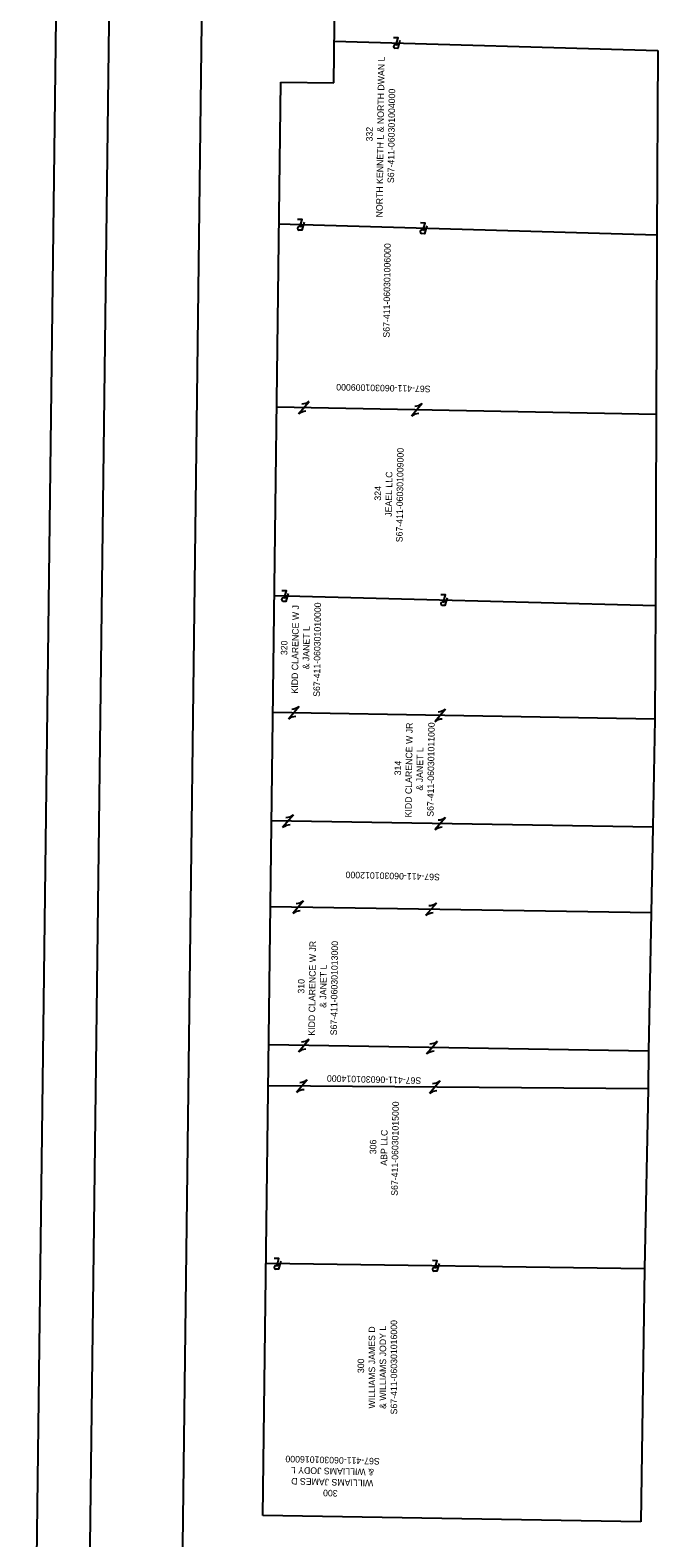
# Model space of a CAD drawing. Extents: x 1652206 to 1653153, y 604222 to 614600.
# Drawn here: x 1652507 to 1652744, y 607973 to 608542 of the extents above; entities that cross this region are included whole.
import ezdxf

# ---------------------------------------------------------------- set-up
doc = ezdxf.new("R2010")
doc.units = 0
for name, color, linetype in [('_CIVIL_CONSTRUCTION', 7, 'Continuous'), ('DT_X_Contour_Minor', 7, 'Continuous'), ('GE_P_Alignment_100_Bearings', 7, 'Continuous'), ('GE_P_Alignment_100_Cardinal_Points', 7, 'Continuous'), ('GE_P_Alignment_100_Distances', 7, 'Continuous')]:
    doc.layers.add(name, color=color, linetype=linetype)

msp = doc.modelspace()

# ---------------------------------------------------------------- linework, layer by layer
at = {"layer": '_CIVIL_CONSTRUCTION'}
msp.add_line((1652550.86, 606872.07), (1652575.14, 608815.48), dxfattribs=at)
at = {"layer": 'DT_X_Contour_Minor'}
msp.add_lwpolyline([(1652527.01, 607765.18), (1652507.01, 607765.43), (1652518.27, 608666.13)], dxfattribs=at)
at = {"layer": 'GE_P_Alignment_100_Bearings'}
for p, q in [((1652621.66, 608537.35), (1652743.59, 608533.88)), ((1652645.94, 608536.04), (1652644.64, 608536.07)), ((1652645.15, 608536.68), (1652645.15, 608536.68)), ((1652743.59, 608533.88), (1652743.27, 608464.32)), ((1652743.27, 608464.32), (1652600.8, 608468.46)), ((1652609.78, 608467.57), (1652608.48, 608467.61)), ((1652608.99, 608468.22), (1652608.99, 608468.22)), ((1652656.06, 608466.23), (1652654.76, 608466.27)), ((1652655.27, 608466.88), (1652655.27, 608466.88)), ((1652743.27, 608464.32), (1652742.93, 608396.68)), ((1652742.93, 608396.68), (1652599.94, 608399.55)), ((1652608.13, 608396.99), (1652612.23, 608401.7)), ((1652610.18, 608399.35), (1652610.18, 608399.35)), ((1652654.8, 608400.85), (1652650.71, 608396.13)), ((1652652.76, 608398.49), (1652652.76, 608398.49)), ((1652742.93, 608396.68), (1652742.65, 608324.68)), ((1652742.65, 608324.68), (1652599.05, 608328.4)), ((1652603.79, 608327.66), (1652602.5, 608327.69)), ((1652603.01, 608328.3), (1652603.01, 608328.3)), ((1652663.77, 608326.1), (1652662.48, 608326.14)), ((1652662.99, 608326.75), (1652662.99, 608326.75)), ((1652742.65, 608324.68), (1652742.51, 608281.9)), ((1652742.51, 608281.9), (1652598.5, 608284.5)), ((1652608.43, 608286.72), (1652604.34, 608281.99)), ((1652606.39, 608284.36), (1652606.39, 608284.36)), ((1652663.58, 608285.73), (1652659.5, 608281)), ((1652661.54, 608283.36), (1652661.54, 608283.36)), ((1652742.51, 608281.9), (1652741.75, 608241.28)), ((1652741.75, 608241.28), (1652597.99, 608243.6)), ((1652606.24, 608245.86), (1652602.16, 608241.13)), ((1652604.2, 608243.5), (1652604.2, 608243.5)), ((1652663.59, 608244.94), (1652659.51, 608240.21)), ((1652661.55, 608242.57), (1652661.55, 608242.57)), ((1652741.75, 608241.28), (1652741.13, 608208.94)), ((1652741.13, 608208.94), (1652597.59, 608211.29)), ((1652610.09, 608213.49), (1652606.01, 608208.75)), ((1652608.05, 608211.12), (1652608.05, 608211.12)), ((1652660.14, 608212.67), (1652656.06, 608207.93)), ((1652658.1, 608210.3), (1652658.1, 608210.3)), ((1652741.13, 608208.94), (1652740.11, 608156.88)), ((1652740.11, 608156.88), (1652596.94, 608159.21)), ((1652608.11, 608156.63), (1652612.18, 608161.36)), ((1652610.15, 608158.99), (1652610.15, 608158.99)), ((1652656.44, 608155.84), (1652660.52, 608160.58)), ((1652658.48, 608158.21), (1652658.48, 608158.21)), ((1652740.11, 608156.88), (1652739.91, 608142.62)), ((1652739.91, 608142.62), (1652596.75, 608143.82)), ((1652611.47, 608146.1), (1652607.43, 608141.34)), ((1652609.45, 608143.72), (1652609.45, 608143.72)), ((1652661.52, 608145.68), (1652657.48, 608140.92)), ((1652659.5, 608143.3), (1652659.5, 608143.3)), ((1652739.91, 608142.62), (1652738.57, 608074.84)), ((1652738.57, 608074.84), (1652595.91, 608076.8)), ((1652601.01, 608076.11), (1652599.72, 608076.12)), ((1652600.22, 608076.74), (1652600.22, 608076.74)), ((1652660.67, 608075.29), (1652659.37, 608075.31)), ((1652659.87, 608075.92), (1652659.87, 608075.92)), ((1652738.57, 608074.84), (1652737.21, 607979.54))]:
    msp.add_line(p, q, dxfattribs=at)
for points in [[(1652644.86, 608535.73), (1652645.74, 608538.66), (1652643.99, 608538.71)], [(1652646.4, 608537.62), (1652645.54, 608534.67), (1652644.5, 608534.71)], [(1652608.7, 608467.27), (1652609.58, 608470.2), (1652607.83, 608470.25)], [(1652610.24, 608469.15), (1652609.38, 608466.21), (1652608.34, 608466.24)], [(1652654.98, 608465.92), (1652655.86, 608468.86), (1652654.11, 608468.91)], [(1652656.52, 608467.81), (1652655.66, 608464.87), (1652654.62, 608464.9)], [(1652602.72, 608327.35), (1652603.59, 608330.28), (1652601.84, 608330.33)], [(1652604.26, 608329.24), (1652603.4, 608326.29), (1652602.36, 608326.32)], [(1652662.69, 608325.79), (1652663.56, 608328.73), (1652661.82, 608328.78)], [(1652664.23, 608327.68), (1652663.37, 608324.74), (1652662.34, 608324.77)], [(1652599.94, 608075.78), (1652600.77, 608078.73), (1652599.03, 608078.75)], [(1652601.45, 608077.69), (1652600.63, 608074.74), (1652599.6, 608074.75)], [(1652659.59, 608074.97), (1652660.43, 608077.91), (1652658.68, 608077.94)], [(1652661.11, 608076.87), (1652660.29, 608073.92), (1652659.25, 608073.94)]]:
    msp.add_lwpolyline(points, dxfattribs=at)
for centre, radius, start, end in [((1652644.63, 608535.38), 0.69, 88.8416, 259.6987), ((1652608.47, 608466.92), 0.69, 88.8087, 259.6658), ((1652654.75, 608465.58), 0.69, 88.8087, 259.6658), ((1652611.21, 608392.62), 5.34, 92.5458, 125.1883), ((1652609.15, 608406.07), 5.34, 272.5458, 305.1883), ((1652653.78, 608391.77), 5.34, 92.5458, 125.1883), ((1652651.73, 608405.21), 5.34, 272.5458, 305.1883), ((1652602.49, 608327), 0.69, 88.9868, 259.8439), ((1652662.46, 608325.45), 0.69, 88.9868, 259.8439), ((1652607.43, 608277.64), 5.34, 92.6621, 125.3047), ((1652605.35, 608291.08), 5.34, 272.6621, 305.3047), ((1652660.5, 608290.08), 5.34, 272.6621, 305.3047), ((1652662.58, 608276.64), 5.34, 92.6621, 125.3047), ((1652603.15, 608250.21), 5.34, 272.7732, 305.4157), ((1652660.5, 608249.29), 5.34, 272.7732, 305.4157), ((1652605.26, 608236.78), 5.34, 92.7732, 125.4157), ((1652662.6, 608235.86), 5.34, 92.7732, 125.4157), ((1652609.1, 608204.4), 5.34, 92.7574, 125.3999), ((1652607, 608217.84), 5.34, 272.7574, 305.3999), ((1652657.05, 608217.02), 5.34, 272.7574, 305.3999), ((1652659.15, 608203.58), 5.34, 92.7574, 125.3999), ((1652609.09, 608165.71), 5.34, 272.765, 305.4075), ((1652657.43, 608164.93), 5.34, 272.765, 305.4075), ((1652611.2, 608152.28), 5.34, 92.765, 125.4075), ((1652659.54, 608151.49), 5.34, 92.765, 125.4075), ((1652610.55, 608137.01), 5.34, 93.2137, 125.8563), ((1652608.34, 608150.43), 5.34, 273.2137, 305.8563), ((1652660.61, 608136.59), 5.34, 93.2137, 125.8563), ((1652658.4, 608150.01), 5.34, 273.2137, 305.8563), ((1652599.71, 608075.43), 0.69, 89.6859, 260.543), ((1652659.37, 608074.62), 0.69, 89.6859, 260.543)]:
    msp.add_arc(centre, radius, start, end, dxfattribs=at)
at = {"layer": 'GE_P_Alignment_100_Distances'}
for p, q in [((1652621.47, 608521.72), (1652624.44, 608759.7)), ((1652525.46, 607640.72), (1652538.25, 608664.92)), ((1652594.72, 607981.92), (1652601.47, 608521.97)), ((1652601.47, 608521.97), (1652621.47, 608521.72)), ((1652737.21, 607979.54), (1652594.72, 607981.92))]:
    msp.add_line(p, q, dxfattribs=at)

# ---------------------------------------------------------------- texts
at = {"layer": 'GE_P_Alignment_100_Cardinal_Points'}
for s, height, rotation, p in [('NORTH KENNETH L & NORTH DWAN L', 2.4653, 89.2843, (1652639.86, 608470.97)), ('S67-411-060301004000', 2.4653, 89.2843, (1652644.17, 608483.92)), ('332', 2.465, 89.2843, (1652636.07, 608499.6)), ('S67-411-060301006000', 2.4653, 89.2843, (1652642.49, 608425.69)), ('S67-411-060301009000', 2.4653, 178.8513, (1652657.96, 608407.57)), ('S67-411-060301009000', 2.4653, 89.2843, (1652647.36, 608348.59)), ('JEAEL LLC', 2.465, 89.2843, (1652643.33, 608358.2)), ('324', 2.465, 89.2843, (1652639.25, 608364.26)), ('KIDD CLARENCE W J', 2.4653, 89.2843, (1652607.93, 608291.58)), ('S67-411-060301010000', 2.4653, 89.2843, (1652616.21, 608290.35)), ('320', 2.465, 89.2843, (1652603.95, 608306.07)), (' & JANET L', 2.465, 89.2843, (1652612.18, 608299.78)), ('KIDD CLARENCE W JR', 2.4653, 89.2843, (1652650.75, 608244.92)), ('S67-411-060301011000', 2.4653, 89.2843, (1652659.05, 608245.17)), ('314', 2.465, 89.2843, (1652646.79, 608260.77)), ('& JANET L', 2.465, 89.2843, (1652655.02, 608255.03)), ('S67-411-060301012000', 2.4653, 178.565, (1652661.48, 608223.65)), ('KIDD CLARENCE W JR', 2.4653, 89.2843, (1652614.32, 608162.68)), ('S67-411-060301013000', 2.4653, 89.2843, (1652622.63, 608162.81)), (' & JANET L', 2.465, 89.2843, (1652618.59, 608172.24)), ('310', 2.465, 89.2843, (1652610.37, 608178.53)), ('S67-411-060301014000', 2.4653, 178.565, (1652654.45, 608146.94)), ('S67-411-060301015000', 2.4653, 89.2843, (1652645.56, 608102.34)), ('ABP LLC', 2.465, 89.2843, (1652641.55, 608113.69)), ('306', 2.465, 89.2843, (1652637.45, 608118.01)), ('WILLIAMS JAMES D', 2.4653, 90, (1652637.04, 608022.21)), ('& WILLIAMS JODY L', 2.4653, 90, (1652641.19, 608022.07)), ('S67-411-060301016000', 2.4653, 90, (1652645.34, 608019.98)), ('300', 2.465, 90, (1652632.89, 608035.55)), ('S67-411-060301016000', 2.4653, 178.565, (1652638.81, 608003.55)), ('& WILLIAMS JODY L', 2.4653, 178.565, (1652636.62, 607999.45)), ('WILLIAMS JAMES D', 2.4653, 178.565, (1652636.38, 607995.3)), ('300', 2.465, 178.565, (1652622.94, 607991.49))]:
    msp.add_text(s, height=height, rotation=rotation, dxfattribs=at).set_placement(p)

doc.saveas('drawing.dxf')
